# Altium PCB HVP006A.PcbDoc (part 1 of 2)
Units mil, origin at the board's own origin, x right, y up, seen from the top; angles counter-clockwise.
Board outline 1253 x 1919 mil, 4 copper layers (Top Layer, Signal Layer 1, Signal Layer 2, Bottom Layer), stack 61.2 mil thick; 55 components, 14 nets, 102 pads, 51 vias.
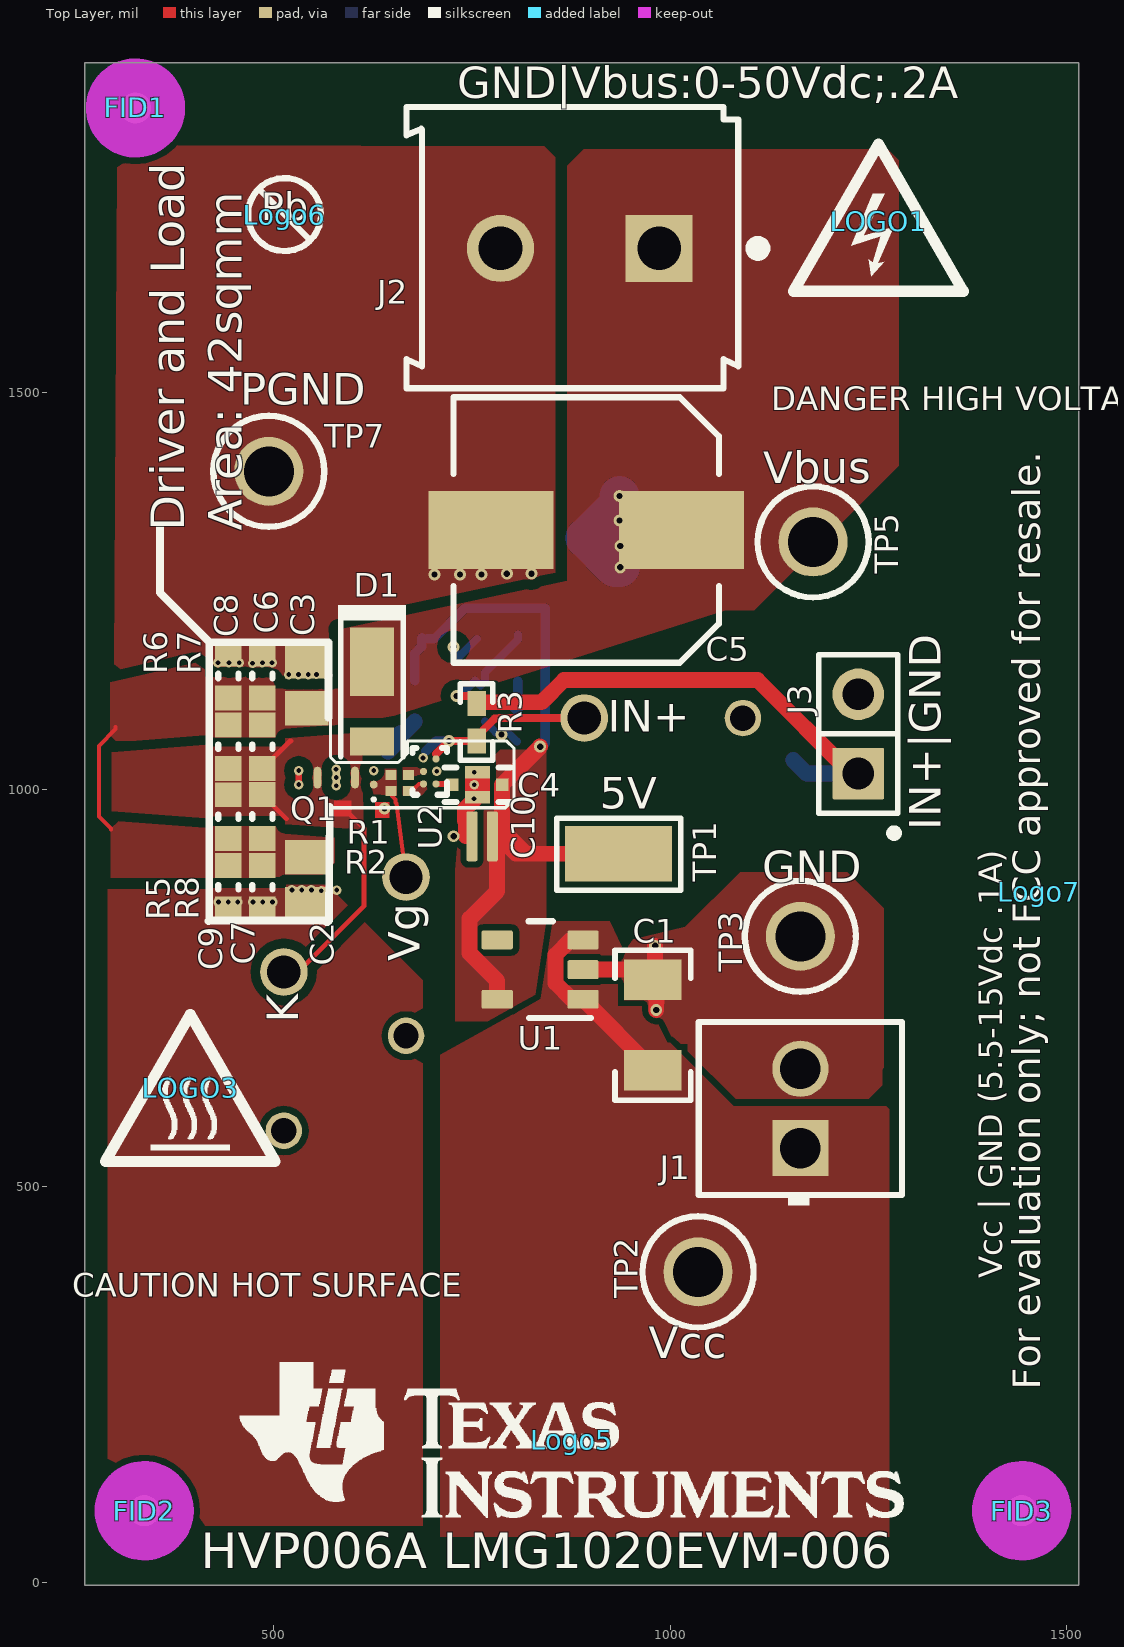
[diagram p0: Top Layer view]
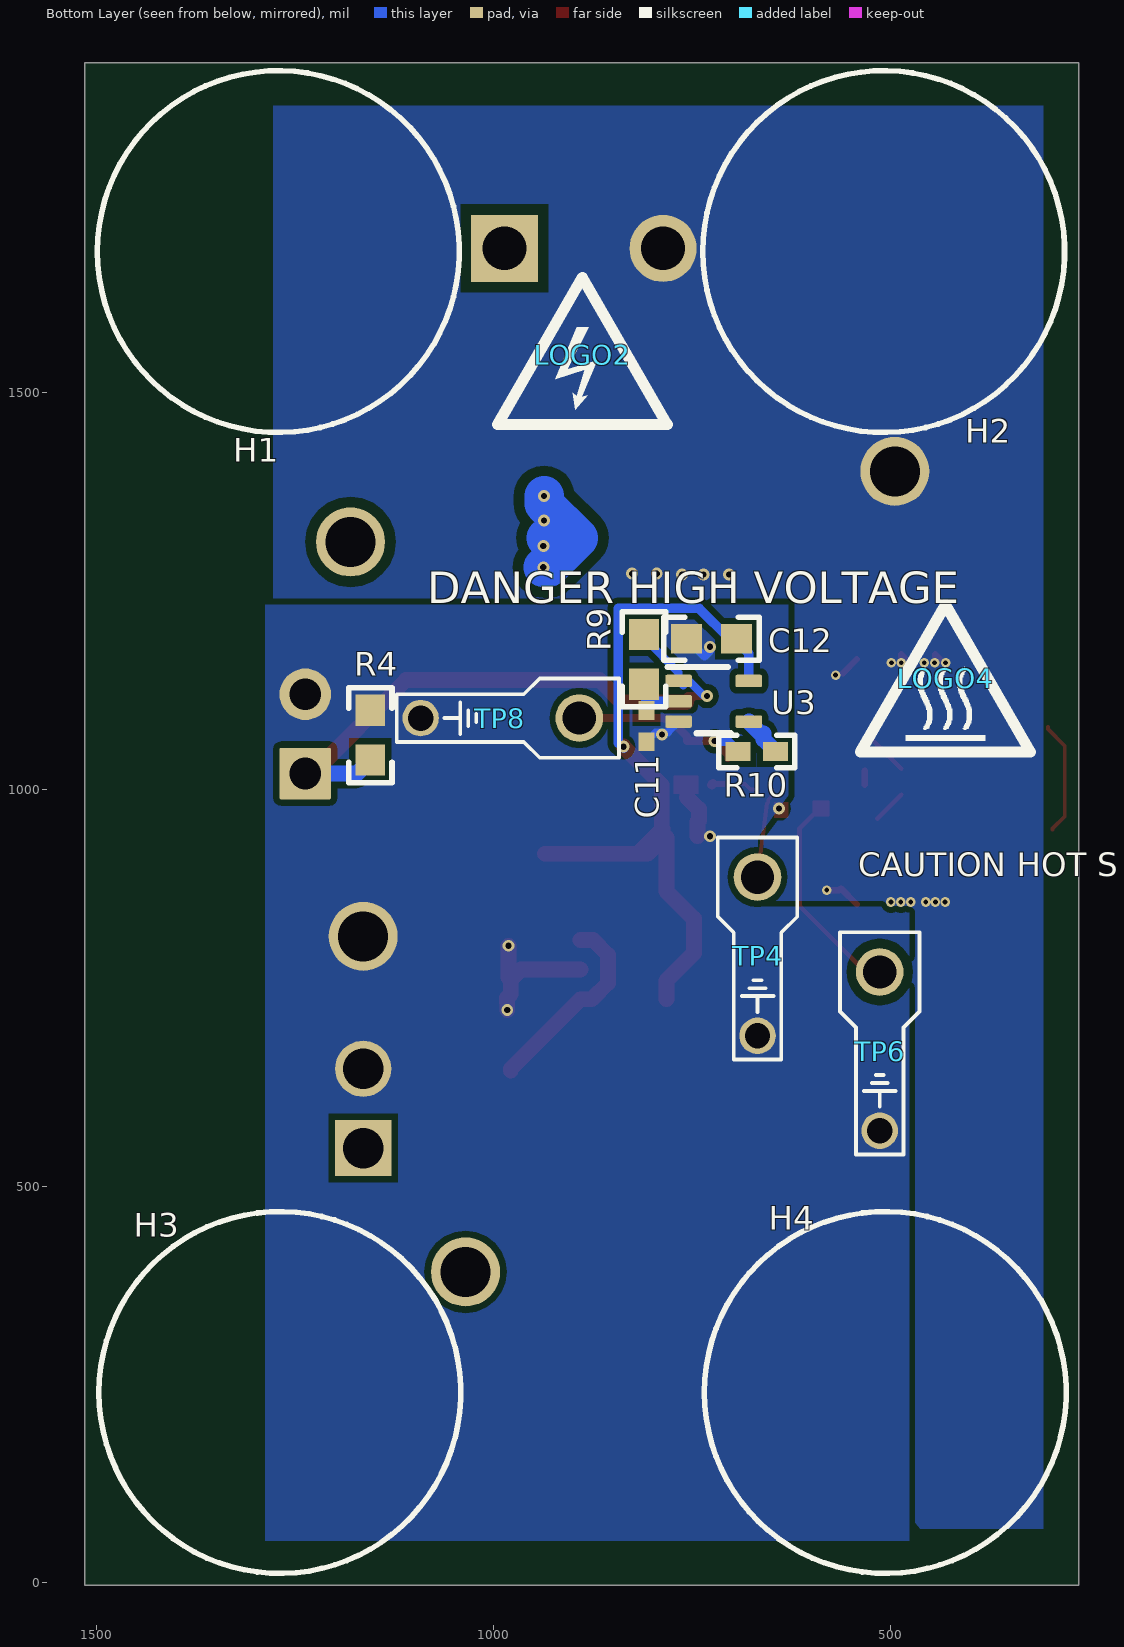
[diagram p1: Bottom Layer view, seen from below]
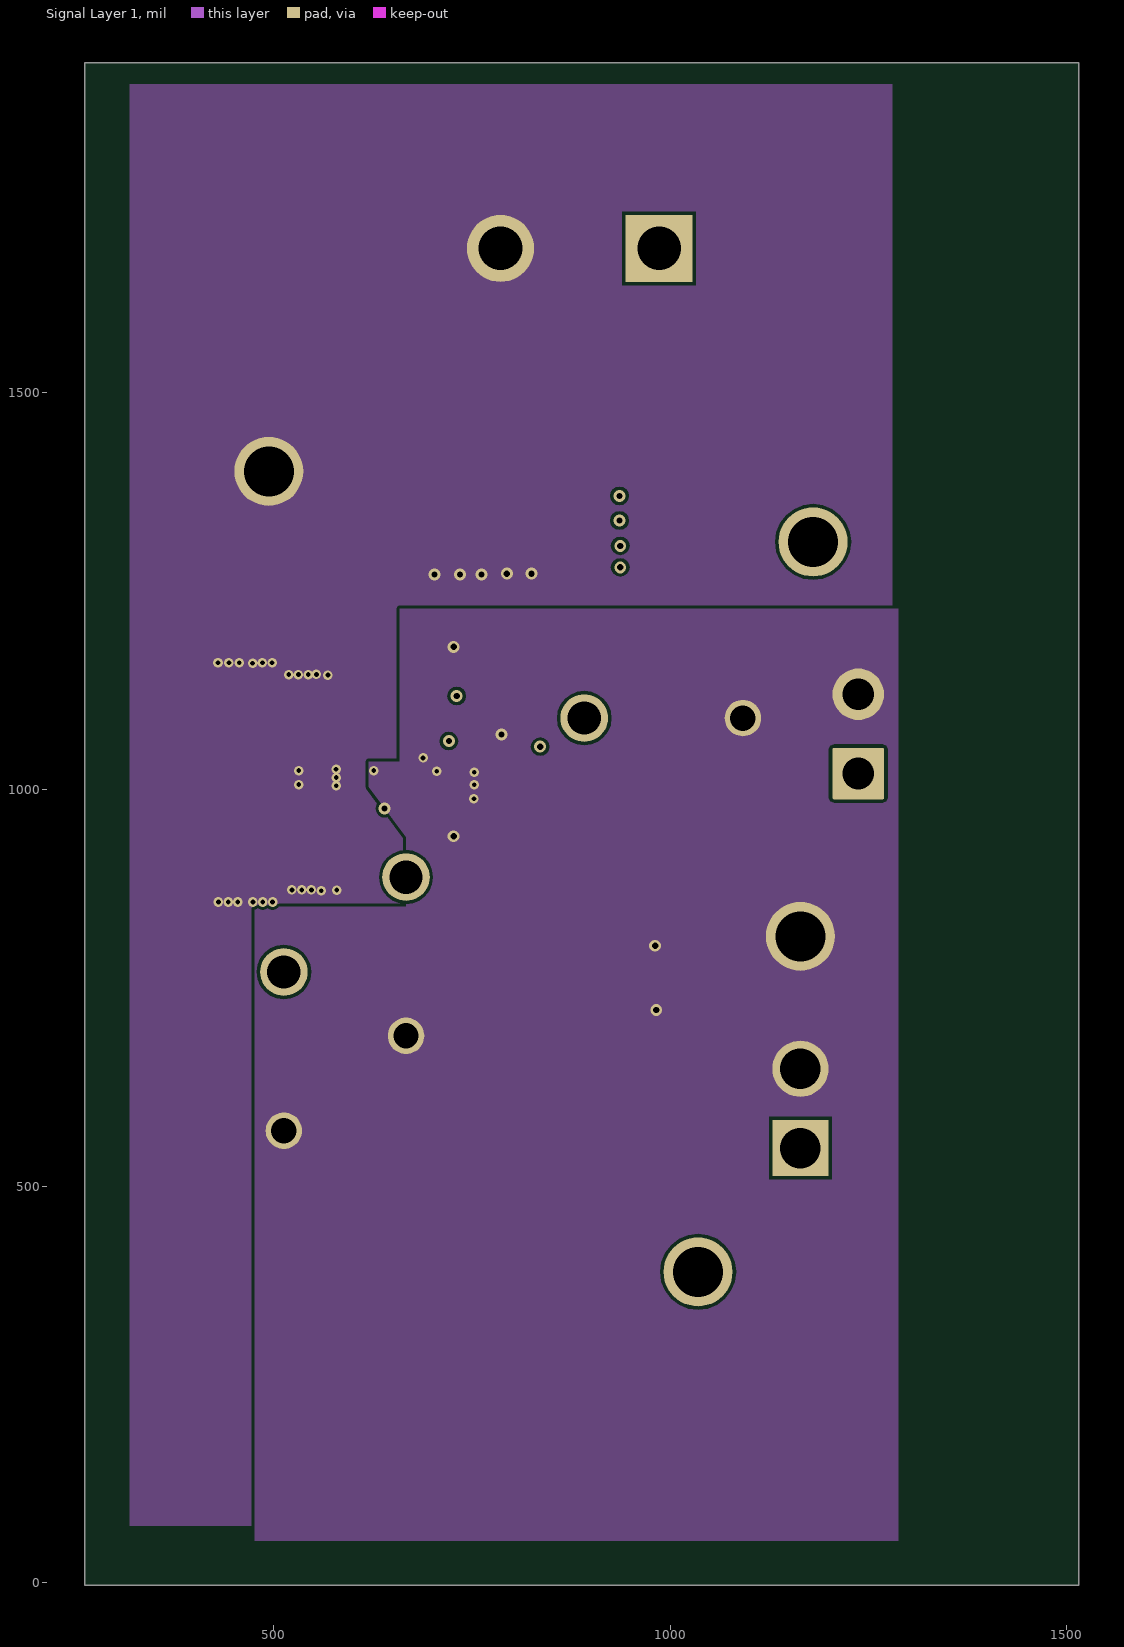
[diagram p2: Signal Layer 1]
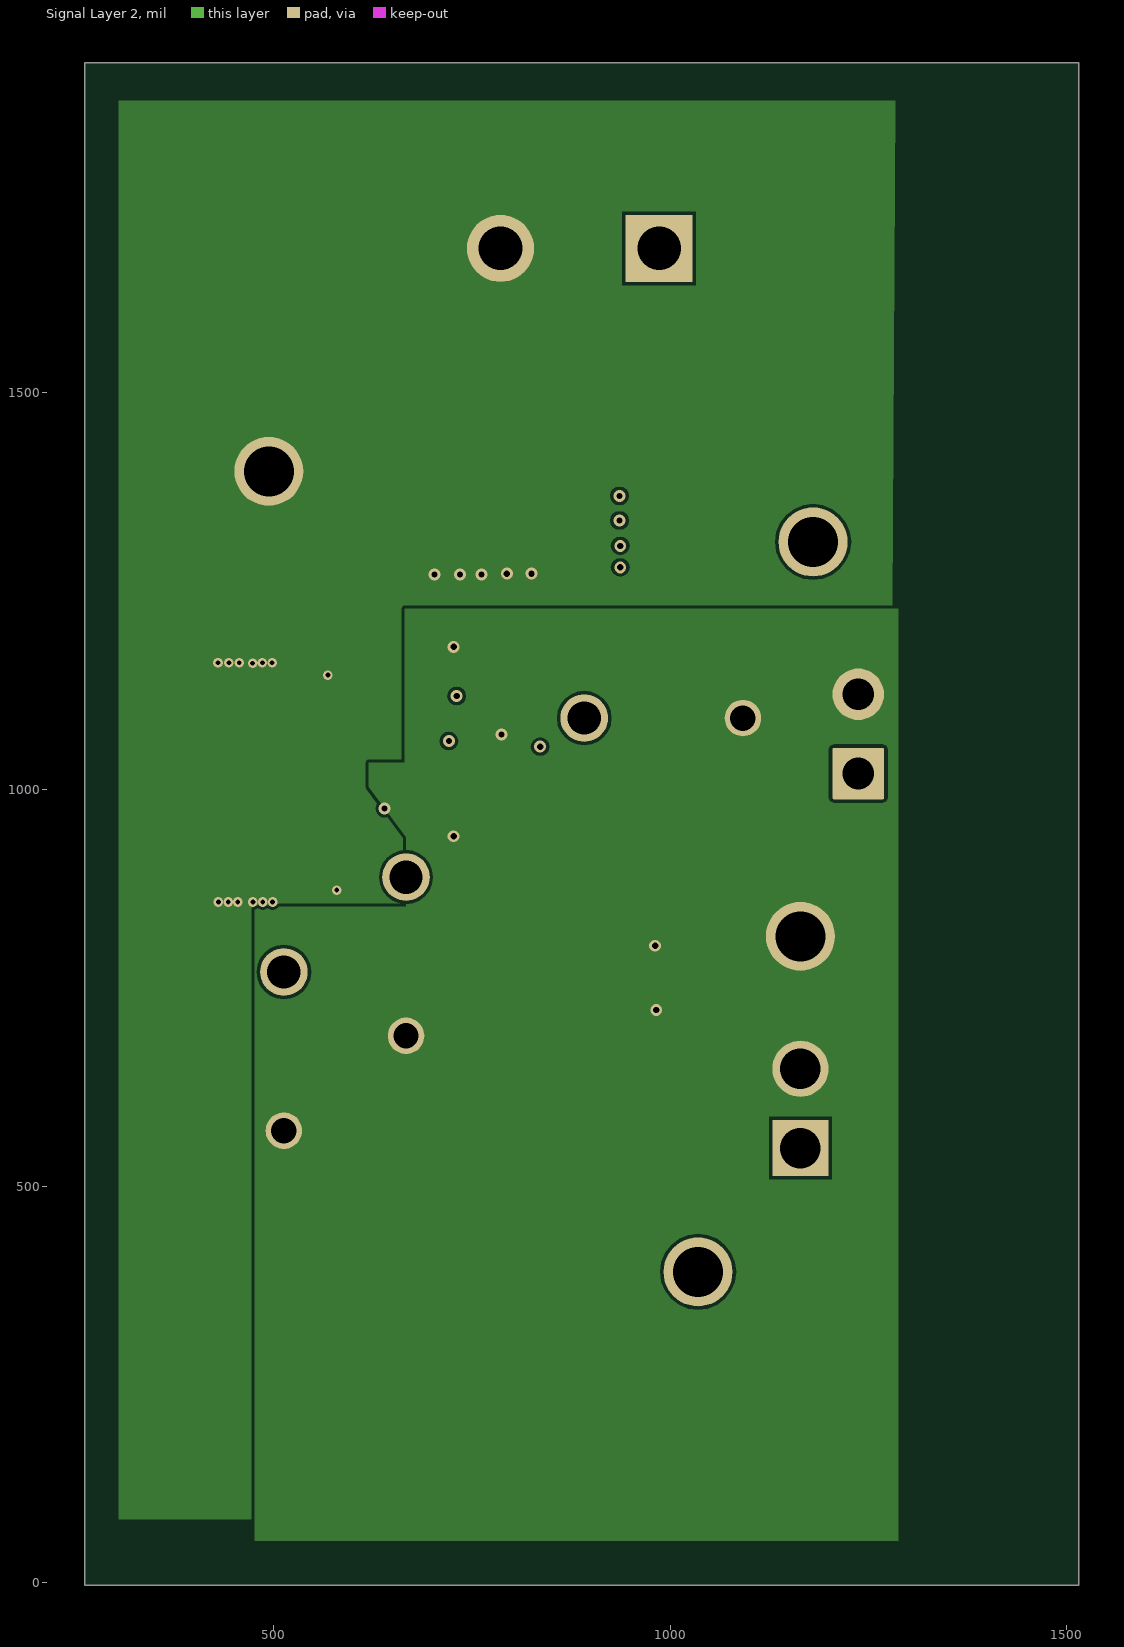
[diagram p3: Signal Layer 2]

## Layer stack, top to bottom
Top Solder: solder mask 0.4, Solder Resist, Dk 3.5
Top Layer: signal copper 1.4
Dielectric1: prepreg 5, FR-4, Dk 4.2
Signal Layer 1: signal copper 1.4
Dielectric 3: core 45.6, Dk 4.2
Signal Layer 2: signal copper 1.4
Dielectric 2: prepreg 5, Dk 4.2
Bottom Layer: signal copper 1.4
Bottom Solder: solder mask 0.4, Solder Resist, Dk 3.5

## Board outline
262,1916 262,-3 1293,-3 1515,-3 1515,219 1515,1916

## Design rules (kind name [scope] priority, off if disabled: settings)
AcuteAngle [All] p1: minimum=4.50000000000000E+0001 checktracksonly=FALSE
AssemblyTestPointUsage [All] p1: valid=2
BoardOutlineClearance BoardOutlineClearance_2 [OnCopper and InNet('AN')] p1: gap=13 ignorepadtopadclearanceinfootprint=FALSE
BoardOutlineClearance BoardOutlineClearance_MountingHoles [OnCopper and InComponentClass('Mounting Holes')] p2: gap=40 ignorepadtopadclearanceinfootprint=FALSE
BoardOutlineClearance BoardOutlineClearance_Poly [OnCopper and IsPoly] p3: gap=10 ignorepadtopadclearanceinfootprint=FALSE
BoardOutlineClearance [OnCopper and Not InComponentClass('Logo') and not InComponentClass('FiducialMark') and not InRegion(1000,500,4000,800) and not InPoly] p4: gap=75 ignorepadtopadclearanceinfootprint=FALSE
Clearance midlayer [OnLayer('Signal Layer 1')  or OnLayer('Signal Layer 2')] p1: gap=4 ignorepadtopadclearanceinfootprint=FALSE except(0: Arc-Hole Track-Hole SMDPad-Hole THPad-Hole Via-Hole Fill-Hole Poly-Hole Region-Hole Text-Hole)
Clearance SW [InNetClass('SW') vs not(InNetClass('SW'))] p2: gap=12 ignorepadtopadclearanceinfootprint=FALSE
Clearance HV [InNetClass('HV') vs not(InNetClass('HV'))] p3: gap=13 ignorepadtopadclearanceinfootprint=FALSE except(0: Arc-Hole Track-Hole SMDPad-Hole THPad-Hole Via-Hole Fill-Hole Poly-Hole Region-Hole Text-Hole)
Clearance Clearance_Keepouts [((IsTrack Or IsArc) And Not InPoly) And IsFree and IsKeepOut vs ((IsTrack Or IsArc) And Not InPoly) And IsFree and IsKeepOut] p4: gap=0 ignorepadtopadclearanceinfootprint=FALSE
Clearance Clearance_Poly [InPolygon] p5: gap=7.87 ignorepadtopadclearanceinfootprint=FALSE except(0: Arc-Hole Track-Hole SMDPad-Hole THPad-Hole Via-Hole Fill-Hole Poly-Hole Region-Hole Text-Hole)
Clearance Fiducial [InComponentClass('FiducialMark') vs InComponentClass('FiducialMark')] p6: gap=0 ignorepadtopadclearanceinfootprint=FALSE
Clearance [All] p7: gap=5 ignorepadtopadclearanceinfootprint=FALSE except(0: Arc-Hole Track-Hole SMDPad-Hole THPad-Hole Via-Hole Fill-Hole Poly-Hole Region-Hole Text-Hole)
ComponentClearance ComponentClearance_MountingHoles_FiducialMarks [InComponentClass('Mounting Holes') vs InComponentClass('FiducialMark')] p1: gap=50 collisioncheckmode=3 verticalgap=10 showdistances=FALSE
ComponentClearance ComponentClearance_Shunt [InComponentClass('Header') vs InComponentClass('Shunt')] p2: gap=0 collisioncheckmode=3 verticalgap=0 showdistances=FALSE
ComponentClearance ComponentClearance_Logo [InComponentClass('Logo')] p3: gap=50 collisioncheckmode=3 verticalgap=10 showdistances=FALSE
ComponentClearance ComponentClearance_ScrewToNut [(HasFootprint('NY PMS 440 0025 PH')) vs (HasFootprint('Keystone_1902C'))] p4: gap=5 collisioncheckmode=3 verticalgap=10 showdistances=FALSE
ComponentClearance ComponentClearance_MountingHoles [InComponentClass('Mounting Holes')] p5: gap=250 collisioncheckmode=3 verticalgap=100000 showdistances=FALSE
ComponentClearance ComponentClearance_SmallPassives [HasFootprint('0201*') or HasFootprint('0402*')  or HasFootprint('YFF0006AAAA') or  HasFootprint('0508') or HasFootprint('0603*') or HasFootprint('0612') or HasFootprint('0805*') or HasFootprint('0815*') or HasFootprint('0830*') or HasFootprint('1206*') or HasFootprint('1210*') or HasFootprint('1808*') or HasFootprint('1812*') or HasFootprint('1825*') or HasFootprint('2010*') or HasFootprint('2220*') or HasFootprint('2225*') or HasFootprint('2512*') or HasFootprint('2728*') or HasFootprint('3518*') or HasFootprint('YFF18PW') vs HasFootprint('0201*')  or HasFootprint('YFF18PW') or HasFootprint('YFF0006AAAA') or HasFootprint('0402*') or HasFootprint('0508') or HasFootprint('0603*') or HasFootprint('0612') or HasFootprint('0805*') or HasFootprint('0815*') or HasFootprint('0830*') or HasFootprint('1206*') or HasFootprint('1210*') or HasFootprint('1808*') or HasFootprint('1812*') or HasFootprint('1825*') or HasFootprint('2010*') or HasFootprint('2220*') or HasFootprint('2225*') or HasFootprint('2512*') or HasFootprint('2728*') or HasFootprint('3518*')] p6: gap=5 collisioncheckmode=3 verticalgap=10 showdistances=FALSE
ComponentClearance ComponentClearance_THtoSMT [IsThruComponent vs IsSMTComponent] p7: gap=10 collisioncheckmode=3 verticalgap=30 showdistances=FALSE
ComponentClearance ComponentClearance_THtoTH [IsThruComponent vs IsThruComponent] p8: gap=30 collisioncheckmode=3 verticalgap=30 showdistances=FALSE
ComponentClearance [All] p9: gap=10 collisioncheckmode=3 verticalgap=10 showdistances=FALSE
DiffPairsRouting [All] p1: maxlimit=100 minlimit=10 mostfreqgap=10 toplayer_minwidth=15 toplayer_maxwidth=15 toplayer_prefwidth=15 midlayer1_minwidth=15 midlayer1_maxwidth=15 midlayer1_prefwidth=15 midlayer2_minwidth=15 midlayer2_maxwidth=15 midlayer2_prefwidth=15 bottomlayer_minwidth=15 bottomlayer_maxwidth=15 bottomlayer_prefwidth=15 maxuncoupledlength=1000
FabricationTestPointUsage TestPointUsage [All] p1: valid=2 allowmultiple=FALSE
FabricationTestpoint Testpoint [All] p1: side=3 testpointundercomponent=TRUE minsize=40 maxsize=100 preferedsize=60 minholesize=0 maxholesize=40 preferedholesize=32 testpointgrid=1 allowsidetop=TRUE allowsidebottom=TRUE usegrid=TRUE gridtolerance=0.01
FanoutControl Fanout_LCC [IsLCC] p1: bgadir=Out bgaviamode=Centered fanoutstyle=Auto fanoutdirection=Alternating viagrid=1 // Fanout_LCC (Default Rule)
FanoutControl Fanout_BGA [IsBGA] p2: bgadir=Out bgaviamode=Centered fanoutstyle=Auto fanoutdirection=Alternating viagrid=1 // Fanout_BGA (Default Rule)
FanoutControl Fanout_Default [All] p4: bgadir=Out bgaviamode=Centered fanoutstyle=Auto fanoutdirection=Alternating viagrid=1 // Fanout_Default (Default Rule)
FanoutControl Fanout_Small [(CompPinCount < 5)] p5: bgadir=Out bgaviamode=Centered fanoutstyle=Auto fanoutdirection=OutThenIn viagrid=1 // Fanout_Small (Default Rule)
HoleSize [All] p1: absolutevalues=TRUE maxlimit=251 minlimit=5.99 maxpercent=80.000 minpercent=20.000
HoleToHoleClearance microviaToMicrovia [not InDrillLayerPair('top to bottom') vs not InDrillLayerPair('top to bottom')] p1: gap=4 allowstackedmicrovias=TRUE
HoleToHoleClearance [All] p2: gap=6 allowstackedmicrovias=FALSE
MinimumAnnularRing MinimumAnnularRing_ThermalPadVias [IsVia and InAnyComponent] p1: minimumring=5.91
MinimumAnnularRing [All] p2: minimumring=3
MinimumSolderMaskSliver MinimumSolderMaskSliver_Logo [InComponentClass('Logo') vs InComponentClass('Logo')] p1: minsoldermaskwidth=0.7
MinimumSolderMaskSliver [All] p2: minsoldermaskwidth=3.73
PlaneConnect [All] p1: planeconnectstyle=Relief reliefexpansion=10 reliefentries=4 reliefconductorwidth=10 reliefairgap=10
PolygonConnect [All] p1: connectstyle=Direct reliefconductorwidth=10 reliefentries=4 polygonreliefangle="90 Angle" airgapwidth=10
RoutingVias ThermalPadVias [IsVia and InAnyComponent] p1: holewidth=4.8 width=19.68 viastyle="Through Hole" minholewidth=5 minwidth=10 maxholewidth=12.99 maxwidth=23.62
RoutingVias [All] p2: holewidth=9 width=15 viastyle="Through Hole" minholewidth=5 minwidth=10 maxholewidth=40 maxwidth=65
SilkToBoardRegionClearance [Not ((IsComment or IsDesignator) And (Hide <> 'False')) and not InRegion(1000,500,4000,800)] p1:
SilkToSilkClearance SilkToSilkClearance_Pb-FreeLogo [(HasFootprint('Pb-Free_Overlay_Medium') OR HasFootprint('Pb-Free_Overlay_Small')) vs (HasFootprint('Pb-Free_Overlay_Medium') OR HasFootprint('Pb-Free_Overlay_Small'))] p1: silktosilkclearance=0
SilkToSilkClearance [All] p2: silktosilkclearance=4
SilkToSolderMaskClearance SilkToComponentPadClearance [IsPad and InAnycomponent] p1: minsilkscreentomaskgap=5 clearancetoexposedcopper=TRUE
SilkToSolderMaskClearance "Silk to Solder Mask Opening" [All] p2: minsilkscreentomaskgap=4 clearancetoexposedcopper=FALSE
SolderMaskExpansion [All] p1: expansion=1.97
Width [All] p1: maxlimit=100 minlimit=5 preferedwidth=10 minimp=50.000000 maximp=50.000000 favimp=50.000000 checkconnectedcopper=TRUE
14 further rules are at their usual default settings.

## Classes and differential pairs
component class HVP006A_EVM_Hardware: !PCB FID1 FID2 FID3 H1 H2 H3 H4 LOGO1 LOGO2 LOGO3 LOGO4 Logo5 Logo6 Logo7 ZZ1 ZZ2 ZZ3
component class Header: J3
component class HVP006A: C1 C2 C3 C4 C5 C6 C7 C8 C9 C10 C11 C12 D1 J1 J2 J3 Q1 R1 R2 R3 R4 R5 R6 R7 R8 R9 R10 TP1 TP2 TP3 TP4 TP5 TP6 TP7 TP8 U1 U2 U3
component class Logo: Logo5
component class FiducialMark: FID1 FID2 FID3
component class AssemblyNote: ZZ1 ZZ2 ZZ3
net class HV: AN
net class SW: KA

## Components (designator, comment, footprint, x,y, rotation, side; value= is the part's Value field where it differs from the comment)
C1 "footprint" 1206 978,703 r270 top value=10uF
C2 "C0805C103F1GACTU" 0805L 542,885 r270 top value=0.01uF
C3 "C0805C103F1GACTU" 0805L 542,1132 r90 top value=0.01uF
C4 "YFF18PW0J474M" YFF18PW 757,1006 r180 top value=0.47uF
C5 "DNP" UUX_800x620 894,1327 r180 top value=4.7uF
C6 "GRM188R72A104KA35D" 0603L 486,1143.05 r90 top value=0.1uF
C7 "GRM188R72A104KA35D" 0603L 486,876.81 r270 top value=0.1uF
C8 "GRM188R72A104KA35D" 0603L 443,1143.05 r90 top value=0.1uF
C9 "GRM188R72A104KA35D" 0603L 443,876.81 r270 top value=0.1uF
C10 "LWK107BJ225MV" 0306 763,941 r180 top value=2.2uF
C11 "GRM1555C1H200JA01D" 0402L 807,1080 r270 bottom value=20pF
C12 "footprint" 0603 725,1190 r0 bottom value=0.1uF
D1 "DFLS2100-7" PowerDI123 624,1110.8 r270 top value=100V
FID1 "Fiducial" Fiducial10-30 326,1859 r0 top
FID2 "Fiducial" Fiducial10-30 337,91 r0 top
FID3 "Fiducial" Fiducial10-30 1443,91 r0 top
H1 "SJ-5303 (CLEAR)" Bumpon_SJ5003Transparent 1271,1678 r90 bottom
H2 "SJ-5303 (CLEAR)" Bumpon_SJ5003Transparent 508,1678 r90 bottom
H3 "SJ-5303 (CLEAR)" Bumpon_SJ5003Transparent 1269,240 r90 bottom
H4 "SJ-5303 (CLEAR)" Bumpon_SJ5003Transparent 506,240 r90 bottom
J1 "Vcc | GND (5.5-15Vdc .1A)" On-Shore_OSTVN02A150 1164,598 r90 top
J2 "GND|Vbus:0-50Vdc;.2A" TEC_282841-2 886,1682 r180 top
J3 "IN+|GND" Samtec_HTSW-102-07-G-S 1237,1070 r90 top
LOGO1 "DANGER HIGH VOLTAGE" IEC_HighVoltage_Small 1262.4,1716 r0 top
LOGO2 "DANGER HIGH VOLTAGE" IEC_HighVoltage_Small 887.8,1547.8 r180 bottom
LOGO3 "CAUTION HOT SURFACE" IEC_HotSurface_Small 395,624 r0 top
LOGO4 "CAUTION HOT SURFACE" IEC_HotSurface_Small 430.2,1140.48 r180 bottom
Logo5 "HVP006A LMG1020EVM-006" TI_Stacked_Overlay_Small 876,180 r0 top
Logo6 "Pb-Free Symbol" Pb-Free_Overlay_Small 513.8,1724.6 r0 top
Logo7 "FCC Disclaimer" FCC_disclaimer 1464.2,870.4 r90 top
Q1 "EPC2019" EPC2019 579,1015 r180 top value=200V
R1 "ERJ-1GE0R00C" 0201L 659,997.8 r180 top value=0
R2 "ERJ-1GE0R00C" 0201L 659,1018 r180 top value=0
R3 "CRCW040210R0JNED" 0402 756,1085 r90 top value=10
R4 "DNP" 0603 1155,1068.5 r270 bottom value=50
R5 "CRCW06034R02FKEA" 0603L 443,965.8 r270 top value=4.02
R6 "CRCW06034R02FKEA" 0603L 443,1053.81 r90 top value=4.02
R7 "CRCW06034R02FKEA" 0603L 486,1053.81 r90 top value=4.02
R8 "CRCW06034R02FKEA" 0603L 486,965.86 r270 top value=4.02
R9 "CR0603-FX-4991ELF" 0603 810.2,1164 r270 bottom value=4.99k
R10 "CRCW04020000Z0ED" 0402 668,1048 r0 bottom value=0
TP1 "5V" Testpoint_Keystone_Miniature 935,919 r0 top
TP2 "Vcc" Keystone5005 1035,392 r270 top value=Red
TP3 "GND" Keystone5006 1164,815 r270 top value=Black
TP4 "Vg" TP_PIGTAIL 667,889.58 r180 bottom
TP5 "Vbus" Keystone5005 1180,1312 r90 top value=Red
TP6 "K" TP_PIGTAIL 513,770 r180 bottom
TP7 "PGND" Keystone5006 494,1401 r90 top value=Black
TP8 "IN+" TP_PIGTAIL 891.6,1090 r270 bottom
U1 "TPS70950DBVR" DBV0005A_N 836,773 r180 top
U2 "XLMG1020" YFF0006AAAA 696.87,1022.75 r180 top
U3 "SN74LVC1G08DCKR" DCK0005A_N 722.26,1111.16 r180 bottom
ZZ1 "This Assembly Note will show in the PcbDoc and associated outputs" AssemblyNote 185,3829.11 r0 top
ZZ2 "This Assembly Note will show in the PcbDoc and associated outputs" AssemblyNote 185,3740.56 r0 top
ZZ3 "This Assembly Note will show in the PcbDoc and associated outputs" AssemblyNote 185,3652 r0 top

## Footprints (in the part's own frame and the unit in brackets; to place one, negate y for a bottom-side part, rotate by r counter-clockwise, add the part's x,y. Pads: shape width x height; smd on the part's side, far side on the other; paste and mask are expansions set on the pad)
0201L [mm] "Data from Kemet datasheet CC101_COM dated 7/28/11"
  rect 0.36x0.32 smd mask+0.048: 1(-0.28,0) 2(0.28,0)
  body extent -0.31,-0.16 0.31,0.16, height 0.26
0306 [mm] "based on TDK recommendation (similar to Taiyo Yuden and MuRata)"
  rrect29% 0.35x1.6 smd: 1(-0.325,0) 2(0.325,0)
  body extent -0.44,-0.85 0.44,0.85, height 0.6
0402 [mm] "0402 from SM-752 data"
  rect 0.8x0.6 smd: 1(-0.6,0) 2(0.6,0)
  silkscreen extent -1.22,-0.52 1.22,0.52, body extent -0.55,-0.3 0.55,0.3, height 0.6
0402L [mm] "0402 from SM-752 data"
  rect 0.6x0.5 smd: 1(-0.5,0) 2(0.5,0)
  body extent -0.55,-0.3 0.55,0.3, height 0.6
0603 [mm] "0603 from SM-752 data"
  rect 1x0.95 smd: 1(-0.8,0) 2(0.8,0)
  silkscreen extent -1.52,-0.69 1.52,0.69, body extent -0.87,-0.47 0.87,0.47, height 1
0603L [mm] "0603 from SM-752 data"
  rect 0.8x0.85 smd: 1(-0.7,0) 2(0.7,0)
  silkscreen extent -0.07,-0.33 0.07,0.33, body extent -0.87,-0.47 0.87,0.47, height 1
0805L [mm] "0805 from SM-752 data"
  rect 1.1x1.4 smd: 1(-0.75,0) 2(0.75,0)
  body extent -1.1,-0.72 1.1,0.72, height 1.45
1206 [mm] "1206 from SM-752 data"
  rect 1.3x1.85 smd: 1(-1.45,0) 2(1.45,0)
  silkscreen extent -2.4,-1.21 2.4,1.21, body extent -1.7,-0.9 1.7,0.9, height 1.35
AssemblyNote [mil] "Assembly Note"
Bumpon_SJ5003Transparent [mil] "3M Hemispherical Bumpon transparent"
  round 1 on Mech4: 0(0,0)
  silkscreen extent -228,-228 228,228, body extent -219,-219 219,219, height 197
DBV0005A_N [mm] "SOT23, 5-Leads, Body 2.9x1.6mm, Pitch 0.95mm, Lead Span 2.8mm, IPC Medium Density"
  rrect17% 1x0.6 smd: 1(-1.375,0.95) 2(-1.375,0) 3(-1.375,-0.95) 4(1.375,-0.95) 5(1.375,0.95)
  silkscreen extent -1.63,-1.55 0.38,1.55, body extent -1.42,-1.46 1.42,1.46, height 1.09
DCK0005A_N [mm] "SOT353, 5-Leads, Body 2x1.3mm, Pitch 0.65mm, Lead Span 2.1mm, IPC Medium Density"
  rrect25% 0.85x0.4 smd: 1(-1.125,0.65) 2(-1.125,0) 3(-1.125,-0.65) 4(1.125,-0.65) 5(1.125,0.65)
  silkscreen extent -1.48,-1.02 0.55,1.1, body extent -1.14,-1 1.14,1, height 0.95
EPC2019 [mm] "SMD. 7-Leads, Body 2.766x0.95mm"
  round 0.25 smd paste-0.2 mask-0.01: 1(-1.2,0.225) 2(-1.2,-0.225) 6(1.2,-0.225) 7(1.2,0.225)
  rrect100% 0.25x0.7 smd paste-0.2 mask-0.01: 3(-0.6,0) 4(0,0) 5(0.6,0)
  rrect38% 0.23x0.23 on Top Paste: ""(-1.2,-0.225) ""(-1.2,0.225) ""(1.2,-0.225) ""(1.2,0.225)
  rrect38% 0.23x0.68 on Top Paste: ""(-0.6,0) ""(0,0) ""(0.6,0)
  silkscreen extent -1.25,0.65 -1.15,0.75, body extent -1.4,-0.49 1.4,0.49, height 0.82
FCC_disclaimer [mil]
Fiducial10-30 [mm]
  round 1 smd mask+1: 1(0,0)
  Top Layer keep-out circle w1.678: c0,0 r0.75
IEC_HighVoltage_Small [mil]
  silkscreen extent -107,-88 107,97
IEC_HotSurface_Small [mil]
  silkscreen extent -107,-93 107,92
Keystone5005 [mil] "Keystone Compact loops"
  round 87 hole 63: 1(0,0)
  silkscreen extent -70,-70 70,70, body extent -63,-63 62,63, height 225
Keystone5006 [mil] "Keystone Compact loops"
  round 87 hole 63: 1(0,0)
  silkscreen extent -70,-70 70,70, body extent -63,-63 62,63, height 225
On-Shore_OSTVN02A150 [mm] "Terminal Block, 2.54mm, 2-pole, Brass, TH"
  rect 1.8x1.8 hole 1.3: 1(-1.27,0)
  round 1.8 hole 1.3: 2(1.27,0)
  silkscreen extent -3.1,-3.25 2.77,3.25, body extent -2.77,-3.25 2.77,3.25, height 8.51
Pb-Free_Overlay_Small [mil]
  silkscreen extent -46,-46 46,46
PowerDI123 [mm] "Diodes Inc recommended land pattern, document number DS30628 Rev. 6-2"
  rect 2.2x1.4 smd: 1(-1.275,0)
  rect 0.9x1.4 smd: 2(1.275,0)
  silkscreen extent -3.1,-1.09 1.76,1.09, body extent -2.38,-0.97 1.52,0.96, height 1
Samtec_HTSW-102-07-G-S [mm] "Samtec 100mil, 1x2, 230 mil above insulator"
  rrect6% 1.65x1.65 hole 1.016: 1(-1.27,0)
  round 1.65 hole 1.016: 2(1.27,0)
  silkscreen extent -3.3,-1.27 2.54,1.27, body extent -2.54,-1.27 2.54,1.27, height 8.38
TEC_282841-2 [mm] "TE Connectivity"
  rect 2.15x2.15 hole 1.4: 1(-2.54,0)
  round 2.15 hole 1.4: 2(2.54,0)
  silkscreen extent -5.9,-4.52 5.55,4.47, body extent -5.08,-4.52 5.58,4.48, height 15.2
Testpoint_Keystone_Miniature [mil] "Miniature SMT test point"
  rect 135x70 smd: 1(0,0)
  silkscreen extent -78,-46 78,45, body extent -52,-20 52,20, height 61
TI_Stacked_Overlay_Small [mil]
  silkscreen extent -418,-98 418,98
TP_PIGTAIL [mil]
  round 60 hole 42: 1(0,0)
  round 46 hole 32: 2(0,-200)
  silkscreen extent -50,-230 50,50
UUX_800x620 [mm] "SMD, 2-Leads, Dia 8mm"
  rect 4x2.5 smd: 1(-3.05,0) 2(3.05,0)
  silkscreen extent -4.25,-4.25 4.25,4.25, body extent -4.25,-4.25 4.25,4.25, height 6.51
YFF0006AAAA [mm] "DSBGA, 6-Leads, Body 0.8x1.2mm, Pitch 0.4mm"
  round 0.23 smd paste-0.13 mask+0.038: A1(-0.2,0.4) A2(0.2,0.4) B1(-0.2,0) B2(0.2,0) C1(-0.2,-0.4) C2(0.2,-0.4)
  silkscreen extent -0.55,-0.75 0.55,0.75, body extent -0.41,-0.61 0.41,0.61, height 0.63
YFF18PW [mm] "TDK"
  rect 0.4x0.4 smd: 1(-0.8,0) 2(0.8,0)
  rect 0.8x0.4 smd: 3(0,0.4) 3(0,-0.4)
  Top Layer region: -0.4,-0.3 0.4,-0.3 0.4,0.3 -0.4,0.3
  silkscreen extent -1.05,-0.55 1.05,0.55, body extent -0.85,-0.45 0.85,0.45, height 0.7

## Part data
C1: library part 885012208069, "CAP, CERM, 10 µF, 25 V, +/- 10%, X7R, 1206", Cap_Case=1206, Manufacturer="Wurth Elektronik", Supplier Part Number 1=732-7574-1-ND, TempCo=X7R, Tolerance_%=10, Value1=Unknown, Value2=25V, ValueDisplayed=10µF
C2 C3: "CAP, CERM, 0.01 µF, 100 V, +/- 1%, C0G/NP0, 0805", Cap_Case=0805, Manufacturer=Kemet, Supplier Part Number 1=399-11160-1-ND, TempCo=C0G/NP0, Tolerance_%=1, Value1=Unknown, Value2=100V, ValueDisplayed=0.01µF
C4: "Feedthru Capacitor, 0.47uF, 6.3V, SMD", Manufacturer=TDK, Supplier Part Number 1=445-3028-1-ND
C5: library part UUX2A4R7MCL1GS, "CAP, AL, 4.7 µF, 100 V, +/- 20%, SMD", Cap_Case=8x6.2mm, Manufacturer=Nichicon, Supplier Part Number 1=493-6282-1-ND, Tolerance_%=20, Value1=Unknown, Value2=100V, ValueDisplayed=4.7µF
C6 C7 C8 C9: "CAP, CERM, 0.1 µF, 100 V, +/- 10%, X7R, 0603", Cap_Case=0603, Manufacturer=MuRata, Supplier Part Number 1=490-3285-1-ND, TempCo=X7R, Tolerance_%=10, Value1=Unknown, Value2=100V, ValueDisplayed=0.1µF
C10: library part LWK107BJ105MV, "CAP, CERM, 1 µF, 10 V, +/- 20%, X5R, 0306", Cap_Case=0306, Manufacturer="Taiyo Yuden", TempCo=X5R, Tolerance_%=20, Value1=Unknown, Value2=10V, ValueDisplayed=2.2µF
C11: "CAP, CERM, 20 pF, 50 V, +/- 5%, C0G/NP0, 0402", Cap_Case=0402, Manufacturer=MuRata, Supplier Part Number 1=81-GRM1555C1H200JA1D, TempCo=C0G/NP0, Tolerance_%=5, Value1=Unknown, Value2=50V, ValueDisplayed=20pF
C12: library part GRM188R71E104KA01D, "CAP, CERM, 0.1uF, 25V, +/-10%, X7R, 0603", Cap_Case=0603, Manufacturer=MuRata, Supplier Part Number 1=490-1524-1-ND, TempCo=X7R, Tolerance_%=10, Value1=Unknown, Value2=25V, ValueDisplayed=0.1µF
D1: "Diode, Schottky, 100 V, 2 A, PowerDI123", Manufacturer="Diodes Inc.", Supplier Part Number 1=DFLS2100-7DICT-ND, Value1=2A, Value2=0.86V
FID1 FID2 FID3: "Fiducial mark.  There is nothing to buy or mount.", Manufacturer=N/A
H1 H2 H3 H4: "Bumpon, Hemisphere, 0.44 X 0.20, Clear", Manufacturer=3M, Supplier Part Number 1=SJ5303-7-ND
J1: library part OSTVN02A150, "Terminal Block, 2.54mm, 2x1, Brass, TH", Manufacturer="On-Shore Technology", Supplier Part Number 1=ED10561-ND
J2: library part 282841-2, "Terminal Block, 2x1, 5.08mm, TH", Manufacturer="TE Connectivity", Supplier Part Number 1=A98342-ND
J3: library part HTSW-102-07-G-S, "Header, 100mil, 2x1, Gold, TH", Manufacturer=Samtec, Supplier Part Number 1=SAM8736-ND
LOGO1 LOGO2: library part IEC_HighVoltage, "IEC 61010-1 High Voltage Warning"
LOGO3 LOGO4: library part IEC_HotSurface, "IEC 61010-1 Hot Surface Warning"
Logo5: library part TI_Logo, "Texas Instrument Corporate Signature"
Logo6: library part Pb-Free
Logo7: library part FCC_disclaimer, "FCC_disclaimer"
Q1: "MOSFET, N-CH, 200 V, 8.5 A, 2.766x0.68mm", Alternate Manufacturer=None, Manufacturer=EPC, Supplier Part Number 1=917-1087-1-ND, Value1="? ohm", Value2="1.8 nC"
R1 R2: library part CMP-0027011-3, "RES, 0, 5%, 0.05 W, 0201", Manufacturer=Panasonic, Power_W=50mW, Supplier Part Number 1=P0.0AGCT-ND, TempCo="600 ppm/C", Tolerance_%=5%, Value2=0.05W, Value_Code=0000, ValueDisplayed=0
R3: "RES, 10, 5%, 0.063 W, 0402", Manufacturer=Vishay-Dale, Power_W=0.063, Supplier Part Number 1=541-10JCT-ND, TempCo="200 ppm/C", Tolerance_%=5, Value1=5%, Value2=0.063W, Value_Code=10R0, ValueDisplayed=DNP
R4: library part CRCW060350R0FKEA, "RES, 50, 1%, 0.1 W, 0603", Manufacturer=Vishay-Dale, Power_W=0.1, Supplier Part Number 1=71-CRCW0603-50-E3, TempCo="100 ppm/C", Tolerance_%=1, Value1=1%, Value2=0.1W, Value_Code=50R0, ValueDisplayed=50
R5 R6 R7 R8: library part CMP-0022469-2, "RES, 4.02, 1%, 0.1 W, 0603", Manufacturer=Vishay-Dale, Power_W=100mW, Supplier Part Number 1=541-4.02HHCT-ND, TempCo="100 ppm/C", Tolerance_%=1%, Value2=0.1W, Value_Code=4R02, ValueDisplayed=4.02
R9: "RES, 4.99 k, 1%, 0.1 W, 0603", Manufacturer=Bourns, Power_W=0.1, Supplier Part Number 1=CR0603-FX-4991ELFTR-ND, TempCo="100 ppm/C", Tolerance_%=1, Value1=1%, Value2=0.1W, Value_Code=4k99, ValueDisplayed=4.99k
R10: "RES, 0, 5%, 0.063 W, 0402", Manufacturer=Vishay-Dale, Power_W=0.063, Supplier Part Number 1=541-0.0JCT-ND, TempCo="200 ppm/C", Tolerance_%=5, Value1=5%, Value2=0.063W, Value_Code=0000, ValueDisplayed=0
TP1: library part 5015, "Test Point, Miniature, SMT", Manufacturer=Keystone, Supplier Part Number 1=36-5015TR-ND
TP2 TP5: library part 5005, "Test Point, Compact, Red, TH", Manufacturer=Keystone, Supplier Part Number 1=5005K-ND
TP3 TP7: library part 5006, "Test Point, Compact, Black, TH", Manufacturer=Keystone, Supplier Part Number 1=5006K-ND
TP4 TP6 TP8: library part TP_PIGTAIL, "Testpoint PCB footprint for pigtail probe", Alternate Manufacturer=-, Manufacturer="Used in BOM report", PartNumber=N/A
U1: "150-mA, 30-V, 1-uA IQ Voltage Regulators with Enable, DBV0005A (SOT-5)", Alternate Manufacturer="Texas Instruments", Alternate PartNumber=TPS70950DBVT
U2: "High Speed Gate Driver in WCSP Package, YFF", Alternate Manufacturer="Texas Instruments"
U3: "Single 2-Input Positive-AND Gate, DCK0005A (SOT-5)", Alternate Manufacturer="Texas Instruments", Alternate PartNumber=SN74LVC1G08DCKT
ZZ1 ZZ2 ZZ3: library part AssemblyNote

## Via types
v1: diameter 15, hole 7.87, Top Layer to Bottom Layer, tented both sides, 18 vias
v2: diameter 12, hole 6, Top Layer to Signal Layer 1, tented both sides, 18 vias
v3: diameter 12, hole 6, Top Layer to Bottom Layer, tented both sides, 14 vias
v4: diameter 12, hole 6, Top Layer to Signal Layer 1, tented top, 1 vias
